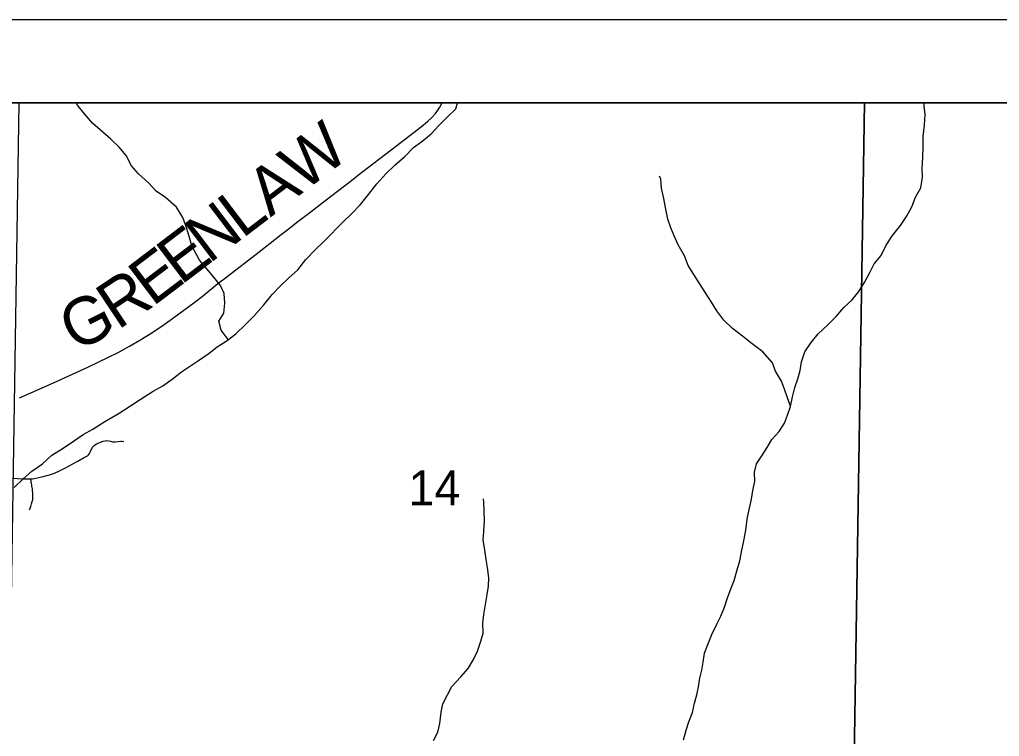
# Model space of a CAD drawing. Extents: x 0 to 34, y -8.9 to 22.
# Drawn here: x 25.767 to 26.944, y 13.144 to 14.004 of the extents above; entities that cross this region are included whole.
import ezdxf

# ---------------------------------------------------------------- set-up
doc = ezdxf.new("R2010")
doc.units = 0
for name, color, linetype in [('GM_X_Corporation', 7, 'Continuous'), ('GM_X_County_Road', 7, 'Continuous'), ('GM_X_County_Road_Text', 7, 'Continuous'), ('GM_X_Minor_River', 7, 'Continuous'), ('GM_X_Section_Text', 7, 'Continuous'), ('GM_X_Township_Road', 7, 'Continuous'), ('SH_Data', 7, 'Continuous')]:
    doc.layers.add(name, color=color, linetype=linetype)

msp = doc.modelspace()

# ---------------------------------------------------------------- linework, layer by layer
at = {"layer": 'GM_X_Corporation'}
for points in [[(28.8143, 13.904), (23.7167, 13.904), (23.7167, 11.9654), (24.1849, 11.9621), (24.2054, 11.9625), (24.3163, 11.9608), (25.0773, 11.948), (25.1035, 11.9505), (25.7218, 11.9377), (25.7578, 11.9372), (26.2139, 11.9314), (27.1396, 11.9157), (27.9423, 11.8981), (28.2591, 11.8967), (28.3241, 11.8942), (28.4085, 11.8914), (28.4711, 11.8911), (28.692, 11.888), (28.7762, 11.8872), (28.7779, 11.9899), (28.7786, 12.0342), (28.7787, 12.0377), (28.8049, 13.053), (28.8122, 13.7561)], [(28.8143, 13.904), (23.7167, 13.904), (23.7167, 11.9654), (24.1849, 11.9621), (24.2054, 11.9625), (24.3163, 11.9608), (25.0773, 11.948), (25.1035, 11.9505), (25.7218, 11.9377), (25.7578, 11.9372), (26.2139, 11.9314), (27.1396, 11.9157), (27.9423, 11.8981), (28.2591, 11.8967), (28.3241, 11.8942), (28.4085, 11.8914), (28.4711, 11.8911), (28.692, 11.888), (28.7762, 11.8872), (28.7779, 11.9899), (28.7786, 12.0342), (28.7787, 12.0377), (28.8049, 13.053), (28.8122, 13.7561)], [(26.7817, 13.904), (25.7664, 13.904), (25.7517, 12.949), (26.7664, 12.9392)], [(27.795, 13.904), (26.7817, 13.904), (26.7664, 12.9392), (27.7795, 12.9249)]]:
    msp.add_lwpolyline(points, close=True, dxfattribs=at)
at = {"layer": 'GM_X_County_Road'}
for points in [[(26.0815, 13.7461), (26.0878, 13.7509), (26.1015, 13.7616), (26.1172, 13.7738), (26.1354, 13.7878), (26.164, 13.8098), (26.1778, 13.8204), (26.2132, 13.8478), (26.2409, 13.8688), (26.2517, 13.8772), (26.2574, 13.882), (26.2624, 13.8866), (26.2666, 13.8912), (26.2696, 13.8952), (26.2719, 13.8988), (26.2741, 13.9033), (26.2744, 13.904)], [(25.7671, 13.5503), (25.8081, 13.5682), (25.8494, 13.587), (25.8741, 13.5988), (25.8857, 13.6047), (25.8993, 13.6121), (25.9116, 13.6194), (25.9259, 13.6283), (25.9409, 13.6383), (25.9525, 13.6465), (25.9766, 13.6642), (25.9863, 13.6719), (26.0051, 13.6872), (26.0145, 13.6943), (26.0548, 13.7255), (26.0815, 13.7461)]]:
    msp.add_lwpolyline(points, dxfattribs=at)
at = {"layer": 'GM_X_Minor_River'}
msp.add_line((26.2911, 13.8971), (26.2929, 13.904), dxfattribs=at)
for points in [[(25.7606, 13.4425), (25.7714, 13.4529), (25.7819, 13.4621), (25.7947, 13.471), (25.806, 13.4814), (25.8195, 13.4899), (25.833, 13.4988), (25.8436, 13.5061), (25.8552, 13.5127), (25.8695, 13.5216), (25.8868, 13.5317), (25.9015, 13.5414), (25.912, 13.5483), (25.9278, 13.558), (25.9391, 13.5646), (25.9504, 13.5727), (25.9616, 13.5812), (25.9714, 13.5878), (25.9819, 13.5951), (25.9947, 13.6036), (26.0045, 13.6113), (26.0165, 13.6191), (26.027, 13.6268), (26.0383, 13.6383), (26.0484, 13.6483), (26.0604, 13.6617), (26.0705, 13.674), (26.0806, 13.6847), (26.0903, 13.6936), (26.1012, 13.7039), (26.1109, 13.7162), (26.1221, 13.7277), (26.1334, 13.7385), (26.1555, 13.7611), (26.1656, 13.7711), (26.1765, 13.7822), (26.1862, 13.7941), (26.1963, 13.8068), (26.2068, 13.819), (26.2176, 13.8294), (26.2296, 13.8398), (26.2401, 13.8505), (26.2503, 13.8579), (26.2615, 13.8671), (26.2705, 13.8771), (26.2803, 13.8867), (26.2911, 13.8971)], [(26.0178, 13.62), (26.0092, 13.6315), (26.0064, 13.6421), (26.0124, 13.6516), (26.0138, 13.6638), (26.0129, 13.6752), (26.0083, 13.685), (26.0006, 13.6951), (25.9922, 13.7049), (25.9834, 13.7154), (25.9741, 13.7327), (25.9714, 13.7425), (25.9682, 13.7535), (25.9632, 13.7667), (25.9555, 13.7791), (25.9425, 13.7904), (25.9311, 13.7982), (25.9219, 13.8083), (25.9101, 13.8188), (25.9017, 13.8285), (25.8951, 13.841), (25.8867, 13.8511), (25.8767, 13.8605), (25.8672, 13.8691), (25.855, 13.8796), (25.8454, 13.8908), (25.837, 13.9013), (25.8351, 13.904)], [(26.825, 13.7568), (26.832, 13.7679), (26.8383, 13.7794), (26.8428, 13.7908), (26.8491, 13.8023), (26.8512, 13.8148), (26.8508, 13.8258), (26.8518, 13.8383), (26.852, 13.8516), (26.8519, 13.8638), (26.8536, 13.8774), (26.8543, 13.8903), (26.8534, 13.9002), (26.8531, 13.904)], [(26.6929, 13.5402), (26.6893, 13.55), (26.6858, 13.5605), (26.6819, 13.5703), (26.6749, 13.582), (26.6714, 13.5922), (26.6596, 13.6053), (26.6466, 13.6151), (26.6352, 13.624), (26.6233, 13.6334), (26.6127, 13.6435), (26.6042, 13.6547), (26.5981, 13.6649), (26.5908, 13.6762), (26.5842, 13.686), (26.5769, 13.698), (26.57, 13.7089), (26.5657, 13.7207), (26.558, 13.7338), (26.553, 13.7444), (26.5491, 13.7542), (26.5456, 13.7644), (26.5428, 13.7784), (26.5408, 13.7894), (26.538, 13.8019), (26.5372, 13.8125), (26.5356, 13.8162)], [(26.5643, 13.1399), (26.5676, 13.1513), (26.5709, 13.1612), (26.575, 13.1726), (26.5775, 13.1837), (26.5804, 13.1939), (26.5822, 13.2034), (26.584, 13.2137), (26.5862, 13.2232), (26.588, 13.2331), (26.5894, 13.2437), (26.5935, 13.254), (26.5983, 13.2662), (26.6042, 13.2784), (26.609, 13.288), (26.6134, 13.299), (26.6167, 13.3089), (26.6212, 13.3208), (26.6252, 13.3311), (26.6289, 13.3436), (26.6318, 13.3547), (26.634, 13.3653), (26.6369, 13.3786), (26.639, 13.3915), (26.6408, 13.4045), (26.6433, 13.4162), (26.6458, 13.4284), (26.6476, 13.4391), (26.6498, 13.4497), (26.6497, 13.4611), (26.6518, 13.471), (26.6586, 13.4805), (26.6649, 13.4905), (26.6705, 13.5), (26.6791, 13.5096), (26.6858, 13.5199), (26.6891, 13.5295), (26.6928, 13.5398), (26.6953, 13.5512), (26.6982, 13.5626), (26.7015, 13.5729), (26.7045, 13.5828), (26.7062, 13.5934), (26.7099, 13.6052), (26.7177, 13.6167), (26.726, 13.627), (26.7376, 13.6378), (26.7477, 13.6478), (26.7567, 13.6585), (26.7668, 13.6677), (26.775, 13.6777), (26.7821, 13.6892), (26.788, 13.7006), (26.7932, 13.7109), (26.8015, 13.7209), (26.8078, 13.7335), (26.8152, 13.745), (26.825, 13.7568)], [(26.2642, 13.1388), (26.2694, 13.1488), (26.272, 13.1594), (26.2734, 13.1731), (26.2755, 13.183), (26.2811, 13.1937), (26.2863, 13.2036), (26.2972, 13.2155), (26.3058, 13.2255), (26.3121, 13.2362), (26.3169, 13.2461), (26.321, 13.2583), (26.3239, 13.2678), (26.3234, 13.2799), (26.3248, 13.2902), (26.3266, 13.302), (26.3287, 13.3141), (26.3301, 13.324), (26.3308, 13.3343), (26.3292, 13.3464), (26.3275, 13.3562), (26.3259, 13.3672), (26.3239, 13.3797), (26.3246, 13.3899), (26.3256, 13.4029), (26.3246, 13.4248), (26.3242, 13.429)]]:
    msp.add_lwpolyline(points, dxfattribs=at)
at = {"layer": 'GM_X_Township_Road'}
for points in [[(25.7806, 13.453), (25.7826, 13.4531), (25.7868, 13.4538), (25.7941, 13.4554), (25.8031, 13.4578), (25.809, 13.4598), (25.8153, 13.4625), (25.8224, 13.4661), (25.8355, 13.4734), (25.8371, 13.4743), (25.8442, 13.4781), (25.8489, 13.4806), (25.8502, 13.4817), (25.8512, 13.4832), (25.8521, 13.4848), (25.853, 13.4868), (25.8534, 13.4878), (25.8539, 13.4888), (25.8544, 13.4898), (25.855, 13.4908), (25.8557, 13.4918), (25.8565, 13.4926), (25.8573, 13.4934), (25.8592, 13.4944), (25.8624, 13.496), (25.8646, 13.4971), (25.8675, 13.4982), (25.8699, 13.4987), (25.8718, 13.4988), (25.8742, 13.4985), (25.8766, 13.498), (25.8789, 13.4975), (25.882, 13.4973), (25.8857, 13.4977), (25.8887, 13.4981), (25.8906, 13.4981), (25.8923, 13.4976)], [(25.7532, 13.4542), (25.7648, 13.4532), (25.7721, 13.4528), (25.7777, 13.4528), (25.7806, 13.453)], [(25.7793, 13.4156), (25.7807, 13.4197), (25.7816, 13.4229), (25.7824, 13.4256), (25.7828, 13.427), (25.783, 13.4279), (25.7831, 13.4287), (25.7832, 13.4295), (25.7832, 13.4304), (25.7832, 13.4315), (25.7832, 13.4324), (25.7832, 13.4335), (25.7832, 13.4346), (25.783, 13.4367), (25.7828, 13.4385), (25.7827, 13.4398), (25.7826, 13.4411), (25.7823, 13.4427), (25.7821, 13.444), (25.7819, 13.4457), (25.7816, 13.4473), (25.7813, 13.4486), (25.781, 13.4503), (25.7806, 13.453)]]:
    msp.add_lwpolyline(points, dxfattribs=at)
at = {"layer": 'SH_Data'}
for points in [[(23.6167, 14.004), (30.6167, 14.004), (30.6167, 7.004), (23.6167, 7.004)], [(23.7167, 13.904), (30.5167, 13.904), (30.5167, 7.104), (23.7167, 7.104)]]:
    msp.add_lwpolyline(points, close=True, dxfattribs=at)

# ---------------------------------------------------------------- texts
at = {"layer": 'GM_X_County_Road_Text'}
for s, rotation, p in [('W', 37.239, (26.1082, 13.7966)), ('A', 37.2396, (26.0684, 13.7664)), ('L', 37.2367, (26.0346, 13.7406)), ('N', 37.2385, (25.9948, 13.7104)), ('E', 37.2357, (25.9609, 13.6847)), ('E', 37.1568, (25.927, 13.6589)), ('R', 33.6841, (25.8851, 13.6309)), ('G', 26.9234, (25.8342, 13.6045))]:
    msp.add_text(s, height=0.0568, rotation=rotation, dxfattribs=at).set_placement(p)
at = {"layer": 'GM_X_Section_Text'}
msp.add_text('14', height=0.04186, rotation=0, dxfattribs=at).set_placement((26.2342, 13.4211))

doc.saveas('drawing.dxf')
